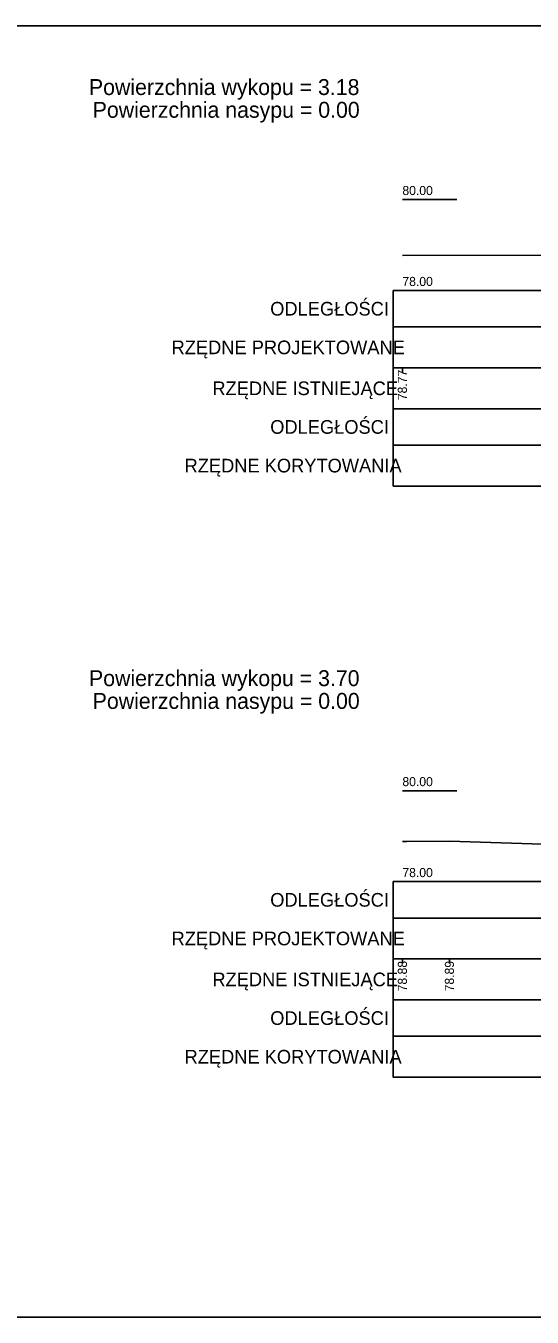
# Model space of a CAD drawing. Extents: x 7492871 to 7493499, y 5802964 to 5802992.
# Drawn here: x 7493426.17 to 7493437.3, y 5802963.88 to 5802992.28 of the extents above; entities that cross this region are included whole.
import ezdxf

# ---------------------------------------------------------------- set-up
doc = ezdxf.new("R2010")
doc.units = 0
for name, color, linetype in [('_wydruk', 7, 'Continuous'), ('d_pop_nasyp_opis', 7, 'Continuous'), ('d_pop_wykop_opis', 7, 'Continuous'), ('pop_opis', 7, 'Continuous'), ('pop_teren', 7, 'Continuous')]:
    doc.layers.add(name, color=color, linetype=linetype)

msp = doc.modelspace()

# ---------------------------------------------------------------- linework, layer by layer
at = {"layer": '_wydruk'}
msp.add_lwpolyline([(7492871.369, 5802992.281), (7493499.283, 5802992.281), (7493499.283, 5802963.881), (7492871.369, 5802963.881)], close=True, dxfattribs=at)
at = {"layer": 'pop_opis'}
for p, q in [((7493434.447, 5802988.459), (7493435.647, 5802988.459)), ((7493434.247, 5802986.459), (7493434.247, 5802984.759)), ((7493434.247, 5802986.459), (7493434.247, 5802984.759)), ((7493434.247, 5802986.459), (7493434.247, 5802984.759)), ((7493434.247, 5802986.459), (7493434.247, 5802984.759)), ((7493434.447, 5802986.459), (7493435.647, 5802986.459)), ((7493434.247, 5802985.659), (7493448.647, 5802985.659)), ((7493434.247, 5802985.659), (7493448.647, 5802985.659)), ((7493434.247, 5802985.659), (7493448.647, 5802985.659)), ((7493434.247, 5802985.659), (7493448.647, 5802985.659)), ((7493434.247, 5802984.759), (7493434.247, 5802983.859)), ((7493434.447, 5802984.659), (7493434.447, 5802984.759)), ((7493434.247, 5802983.859), (7493434.247, 5802982.159)), ((7493434.247, 5802983.059), (7493448.647, 5802983.059)), ((7493434.447, 5802975.459), (7493435.647, 5802975.459)), ((7493434.247, 5802973.459), (7493434.247, 5802971.759)), ((7493434.247, 5802973.459), (7493434.247, 5802971.759)), ((7493434.247, 5802973.459), (7493434.247, 5802971.759)), ((7493434.247, 5802973.459), (7493434.247, 5802971.759)), ((7493434.447, 5802973.459), (7493435.647, 5802973.459)), ((7493434.247, 5802972.659), (7493448.647, 5802972.659)), ((7493434.247, 5802972.659), (7493448.647, 5802972.659)), ((7493434.247, 5802972.659), (7493448.647, 5802972.659)), ((7493434.247, 5802972.659), (7493448.647, 5802972.659)), ((7493434.247, 5802971.759), (7493434.247, 5802970.859)), ((7493434.447, 5802971.659), (7493434.447, 5802971.759)), ((7493435.48, 5802971.659), (7493435.48, 5802971.759)), ((7493434.247, 5802970.859), (7493434.247, 5802969.159)), ((7493434.247, 5802970.059), (7493448.647, 5802970.059))]:
    msp.add_line(p, q, dxfattribs=at)
for points in [[(7493434.247, 5802986.459), (7493434.247, 5802984.759), (7493448.647, 5802984.759), (7493448.647, 5802986.459)], [(7493434.247, 5802986.459), (7493434.247, 5802984.759), (7493448.647, 5802984.759), (7493448.647, 5802986.459)], [(7493434.247, 5802986.459), (7493434.247, 5802984.759), (7493448.647, 5802984.759), (7493448.647, 5802986.459)], [(7493434.247, 5802986.459), (7493434.247, 5802984.759), (7493448.647, 5802984.759), (7493448.647, 5802986.459)], [(7493434.247, 5802984.759), (7493434.247, 5802983.859), (7493448.647, 5802983.859), (7493448.647, 5802984.759)], [(7493434.247, 5802983.859), (7493434.247, 5802982.159), (7493448.647, 5802982.159), (7493448.647, 5802983.859)], [(7493434.247, 5802973.459), (7493434.247, 5802971.759), (7493448.647, 5802971.759), (7493448.647, 5802973.459)], [(7493434.247, 5802973.459), (7493434.247, 5802971.759), (7493448.647, 5802971.759), (7493448.647, 5802973.459)], [(7493434.247, 5802973.459), (7493434.247, 5802971.759), (7493448.647, 5802971.759), (7493448.647, 5802973.459)], [(7493434.247, 5802973.459), (7493434.247, 5802971.759), (7493448.647, 5802971.759), (7493448.647, 5802973.459)], [(7493434.247, 5802971.759), (7493434.247, 5802970.859), (7493448.647, 5802970.859), (7493448.647, 5802971.759)], [(7493434.247, 5802970.859), (7493434.247, 5802969.159), (7493448.647, 5802969.159), (7493448.647, 5802970.859)]]:
    msp.add_lwpolyline(points, close=True, dxfattribs=at)
at = {"layer": 'pop_teren'}
for points in [[(7493434.447, 5802987.226), (7493438.465, 5802987.235), (7493439.442, 5802987.232), (7493439.455, 5802987.229), (7493439.578, 5802987.231), (7493441.742, 5802987.225), (7493443.197, 5802987.203), (7493443.332, 5802987.203), (7493444.392, 5802987.151), (7493444.41, 5802987.155), (7493448.447, 5802987.127)], [(7493434.447, 5802974.341), (7493434.543, 5802974.34), (7493435.48, 5802974.346), (7493438.889, 5802974.243), (7493439.557, 5802974.168), (7493439.76, 5802974.147), (7493440.701, 5802974.156), (7493441.881, 5802974.158), (7493443.283, 5802974.2), (7493443.963, 5802974.196), (7493444.283, 5802974.267), (7493446.059, 5802974.241), (7493447.832, 5802974.233), (7493448.447, 5802974.233)]]:
    msp.add_lwpolyline(points, dxfattribs=at)

# ---------------------------------------------------------------- texts
at = {"layer": 'd_pop_nasyp_opis'}
for p in [(7493427.642, 5802990.259), (7493427.642, 5802977.259)]:
    msp.add_text('Powierzchnia nasypu = 0.00', height=0.35, dxfattribs=at).set_placement(p)
at = {"layer": 'd_pop_wykop_opis'}
for s, p in [('Powierzchnia wykopu = 3.18', (7493427.559, 5802990.759)), ('Powierzchnia wykopu = 3.70', (7493427.561, 5802977.759))]:
    msp.add_text(s, height=0.35, dxfattribs=at).set_placement(p)
at = {"layer": 'pop_opis'}
for s, height, p in [('80.00', 0.2, (7493434.447, 5802988.559)), ('78.00', 0.2, (7493434.447, 5802986.559)), ('ODLEGŁOŚCI', 0.3, (7493431.543, 5802985.909)), ('ODLEGŁOŚCI', 0.3, (7493431.543, 5802985.909)), ('ODLEGŁOŚCI', 0.3, (7493431.543, 5802985.909)), ('ODLEGŁOŚCI', 0.3, (7493431.543, 5802985.909)), ('RZĘDNE PROJEKTOWANE', 0.3, (7493429.375, 5802985.059)), ('RZĘDNE PROJEKTOWANE', 0.3, (7493429.375, 5802985.059)), ('RZĘDNE PROJEKTOWANE', 0.3, (7493429.375, 5802985.059)), ('RZĘDNE PROJEKTOWANE', 0.3, (7493429.375, 5802985.059)), ('RZĘDNE ISTNIEJĄCE', 0.3, (7493430.272, 5802984.159)), ('ODLEGŁOŚCI', 0.3, (7493431.543, 5802983.309)), ('RZĘDNE KORYTOWANIA', 0.3, (7493429.661, 5802982.459)), ('80.00', 0.2, (7493434.447, 5802975.559)), ('78.00', 0.2, (7493434.447, 5802973.559)), ('ODLEGŁOŚCI', 0.3, (7493431.543, 5802972.909)), ('ODLEGŁOŚCI', 0.3, (7493431.543, 5802972.909)), ('ODLEGŁOŚCI', 0.3, (7493431.543, 5802972.909)), ('ODLEGŁOŚCI', 0.3, (7493431.543, 5802972.909)), ('RZĘDNE PROJEKTOWANE', 0.3, (7493429.375, 5802972.059)), ('RZĘDNE PROJEKTOWANE', 0.3, (7493429.375, 5802972.059)), ('RZĘDNE PROJEKTOWANE', 0.3, (7493429.375, 5802972.059)), ('RZĘDNE PROJEKTOWANE', 0.3, (7493429.375, 5802972.059)), ('RZĘDNE ISTNIEJĄCE', 0.3, (7493430.272, 5802971.159)), ('ODLEGŁOŚCI', 0.3, (7493431.543, 5802970.309)), ('RZĘDNE KORYTOWANIA', 0.3, (7493429.661, 5802969.459))]:
    msp.add_text(s, height=height, dxfattribs=at).set_placement(p)
for s, p in [('78.77', (7493434.547, 5802984.047)), ('78.88', (7493434.547, 5802971.046)), ('78.89', (7493435.58, 5802971.046))]:
    msp.add_text(s, height=0.2, rotation=90, dxfattribs=at).set_placement(p)

doc.saveas('drawing.dxf')
